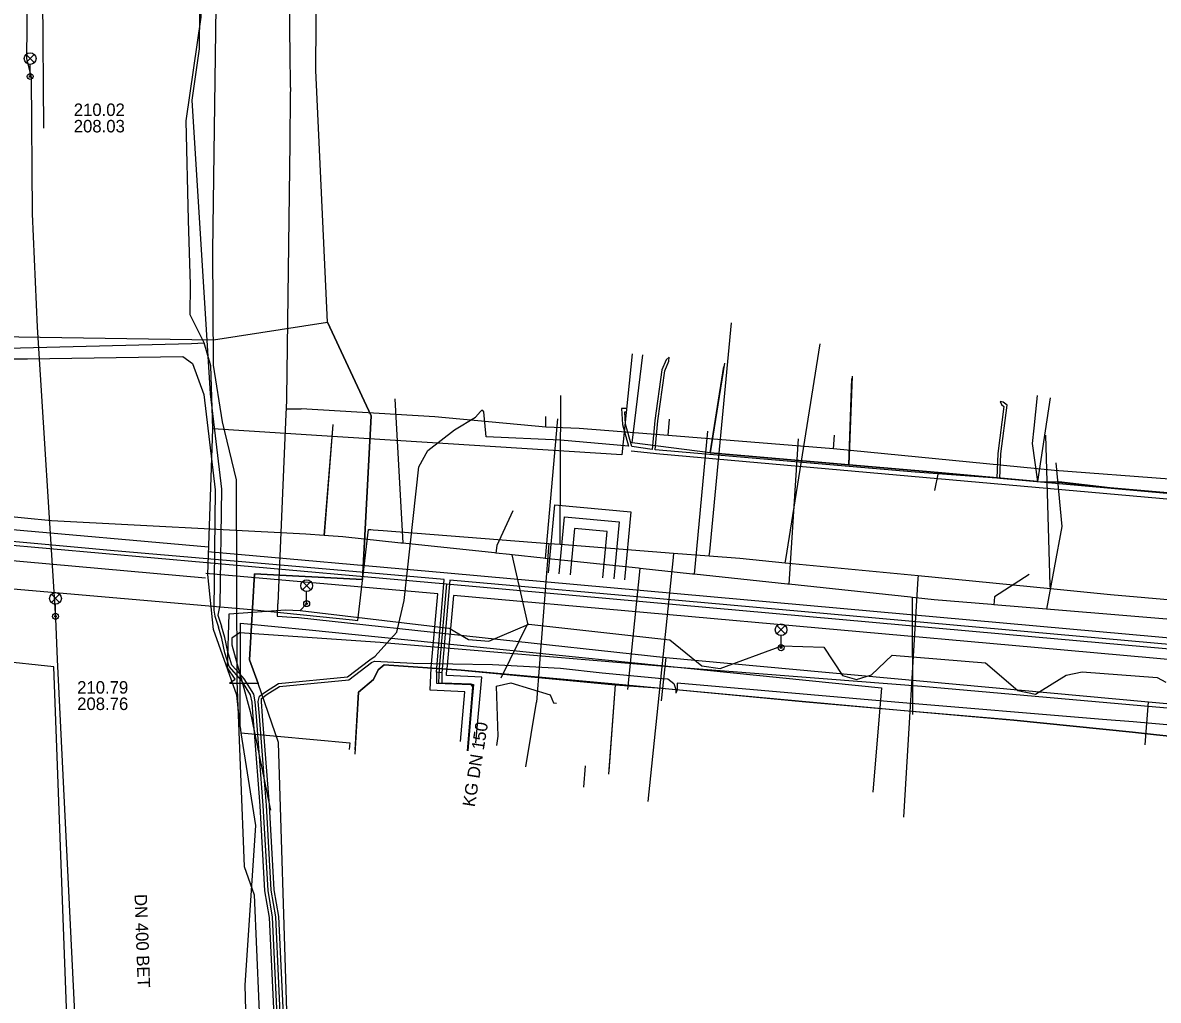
# Model space of a CAD drawing. Extents: x -596228 to -595156, y -1161235 to -1159373.
# Drawn here: x -595381.6 to -595308.9, y -1160980.9 to -1160918.3 of the extents above; entities that cross this region are included whole.
import ezdxf

# ---------------------------------------------------------------- set-up
doc = ezdxf.new("R2010")
doc.units = 0
for name, color, linetype in [('Vrstva 1', 7, 'Continuous'), ('Vrstva 12', 7, 'Continuous'), ('Vrstva 13', 7, 'Continuous'), ('Vrstva 14', 7, 'Continuous'), ('Vrstva 19', 7, 'Continuous'), ('Vrstva 25', 7, 'Continuous'), ('Vrstva 26', 7, 'Continuous'), ('Vrstva 30', 7, 'Continuous'), ('Vrstva 33', 7, 'Continuous'), ('Vrstva 4', 7, 'Continuous'), ('Vrstva 42', 7, 'Continuous'), ('Vrstva 5', 7, 'Continuous'), ('Vrstva 55', 7, 'Continuous'), ('Vrstva 58', 7, 'Continuous'), ('Vrstva 8', 7, 'Continuous'), ('Vrstva 9', 7, 'Continuous')]:
    doc.layers.add(name, color=color, linetype=linetype)

msp = doc.modelspace()

# ---------------------------------------------------------------- linework, layer by layer
at = {"layer": 'Vrstva 1'}
for p, q in [((-595380.27, -1160925.02), (-595380.587, -1160882.118)), ((-595361.765, -1160944.004), (-595362.33, -1160951.115)), ((-595361.77, -1160944), (-595362.315, -1160951.115)), ((-595379.64, -1160959.52), (-595405.794, -1160956.753)), ((-595377.69, -1161011.68), (-595379.64, -1160959.52)), ((-595345.694, -1160967.235), (-595345.58, -1160965.87))]:
    msp.add_line(p, q, dxfattribs=at)
for points in [[(-595350.229, -1160949.537), (-595351.264, -1160951.747), (-595351.317, -1160952.244)], [(-595350.229, -1160949.537), (-595351.264, -1160951.747), (-595351.317, -1160952.244)], [(-595317.17, -1160953.607), (-595319.381, -1160955.051), (-595319.423, -1160955.549)], [(-595317.17, -1160953.61), (-595319.381, -1160955.051), (-595319.423, -1160955.549)], [(-595351.31, -1160960.77), (-595350.37, -1160960.55), (-595347.85, -1160961.31), (-595347.63, -1160961.83), (-595347.442, -1160961.848)]]:
    msp.add_lwpolyline(points, dxfattribs=at)
at = {"layer": 'Vrstva 12'}
for p, q in [((-595336.68, -1160940.07), (-595337.6, -1160945.81)), ((-595328.51, -1160940.91), (-595328.71, -1160946.59)), ((-595316.643, -1160942.14), (-595316.86, -1160944.229)), ((-595316.86, -1160944.229), (-595316.963, -1160945.224)), ((-595316.963, -1160945.224), (-595316.62, -1160947.65)), ((-595337.6, -1160945.81), (-595328.71, -1160946.59)), ((-595328.71, -1160946.59), (-595323, -1160947.07)), ((-595323, -1160947.07), (-595323.22, -1160948.24)), ((-595323, -1160947.07), (-595316.62, -1160947.65)), ((-595343.67, -1160960.68), (-595344.09, -1160966.19))]:
    msp.add_line(p, q, dxfattribs=at)
for points in [[(-595371, -1160930.92), (-595371.16, -1160924.56), (-595370.19, -1160917.92), (-595369.95, -1160902.1), (-595370.25, -1160895.24), (-595369.91, -1160889.72), (-595369.62, -1160887.23)], [(-595369.44, -1160944.29), (-595369.58, -1160940.25), (-595370.01, -1160938.78), (-595370.9, -1160936.97), (-595370.88, -1160935.06), (-595371, -1160930.92)], [(-595342.59, -1160939.47), (-595343.25, -1160945.95), (-595362.46, -1160944.73), (-595369.44, -1160944.29)], [(-595337.6, -1160945.81), (-595342.6, -1160945.18), (-595341.9, -1160939.54)], [(-595367.69, -1160963.36), (-595367.91, -1160961.33), (-595369.41, -1160957.13), (-595369.77, -1160953.61), (-595369.44, -1160944.29)], [(-595316.62, -1160947.65), (-595315.26, -1160947.69), (-595311.97, -1160948.06), (-595303.88, -1160948.77)], [(-595367.69, -1160963.36), (-595367.67, -1160956.73), (-595363.28, -1160957.16), (-595326.63, -1160960.87), (-595327.17, -1160967.55)], [(-595360.33, -1160964.84), (-595360.12, -1160961.14), (-595359.16, -1160960.34), (-595358.85, -1160959.72), (-595358.47, -1160959.4), (-595353.55, -1160959.74), (-595344.12, -1160960.64), (-595343.67, -1160960.68)], [(-595343.67, -1160960.68), (-595340.7, -1160960.9), (-595331.47, -1160961.77), (-595325.4, -1160962.31), (-595318.15, -1160962.95), (-595310.55, -1160963.72), (-595309, -1160963.87), (-595307.34, -1160964.05)], [(-595367.69, -1160963.36), (-595367.65, -1160963.76), (-595366.71, -1160969.68), (-595367.4, -1160979.92), (-595366.8, -1161002.33), (-595366.29, -1161020.66), (-595365.09, -1161023.16)]]:
    msp.add_lwpolyline(points, dxfattribs=at)
at = {"layer": 'Vrstva 13'}
for points in [[(-595395.33, -1160939.24), (-595394.39, -1160939.34), (-595391.91, -1160939.34), (-595370.82, -1160938.81), (-595370.01, -1160938.78)], [(-595367.65, -1160963.76), (-595360.68, -1160964.39), (-595360.72, -1160964.81)]]:
    msp.add_lwpolyline(points, dxfattribs=at)
at = {"layer": 'Vrstva 14'}
for p, q in [((-595401.404, -1160952.842), (-595366.99, -1160955.862)), ((-595366.99, -1160955.862), (-595360.51, -1160956.52)), ((-595349.41, -1160965.94), (-595348.722, -1160961.788))]:
    msp.add_line(p, q, dxfattribs=at)
for points in [[(-595337.656, -1160952.418), (-595337.62, -1160952.14), (-595336.229, -1160937.487)], [(-595332.784, -1160952.855), (-595332.75, -1160952.654), (-595330.552, -1160938.832)], [(-595347.2, -1160951.678), (-595347.198, -1160951.528), (-595347.16, -1160942.15)], [(-595315.808, -1160954.514), (-595315.817, -1160954.307), (-595316.1, -1160944.69)], [(-595360.51, -1160956.52), (-595360.157, -1160956.561), (-595359.48, -1160950.72), (-595359.33, -1160950.733)], [(-595359.33, -1160950.733), (-595359.177, -1160950.746), (-595358.53, -1160950.8), (-595347.93, -1160951.621), (-595347.2, -1160951.678), (-595339.947, -1160952.24), (-595337.656, -1160952.418), (-595335.7, -1160952.57), (-595332.784, -1160952.855), (-595324.277, -1160953.686), (-595315.808, -1160954.514), (-595311.96, -1160954.89), (-595304.861, -1160955.516)], [(-595347.93, -1160951.621), (-595347.95, -1160951.88), (-595348.722, -1160961.788)], [(-595339.947, -1160952.24), (-595339.974, -1160952.52), (-595341.58, -1160968.155)], [(-595324.277, -1160953.686), (-595324.286, -1160953.873), (-595325.222, -1160969.157)]]:
    msp.add_lwpolyline(points, dxfattribs=at)
at = {"layer": 'Vrstva 19'}
for p, q in [((-595364.47, -1160922.43), (-595364.49, -1160922.96)), ((-595348.11, -1160944.18), (-595348.13, -1160943.5)), ((-595340.28, -1160944.7), (-595340.2, -1160943.67)), ((-595329.7, -1160945.56), (-595329.63, -1160944.69)), ((-595340.44, -1160958.93), (-595340.73, -1160961.71)), ((-595309.73, -1160964.53), (-595309.52, -1160961.76))]:
    msp.add_line(p, q, dxfattribs=at)
for points in [[(-595364.47, -1160922.43), (-595364.47, -1160922.01), (-595364.49, -1160920.51), (-595364.54, -1160916.5), (-595367.18, -1160916.4)], [(-595364.49, -1160922.96), (-595364.51, -1160925.89), (-595364.51, -1160925.97), (-595364.73, -1160942.3), (-595364.731, -1160942.38), (-595364.76, -1160943), (-595364.772, -1160943.281), (-595364.774, -1160943.339), (-595365.296, -1160955.473), (-595365.298, -1160955.529), (-595365.33, -1160956.27), (-595364.386, -1160956.339), (-595363.97, -1160956.37)], [(-595364.76, -1160943), (-595364.7, -1160943), (-595364.19, -1160943), (-595363.8, -1160943)], [(-595200.02, -1160957.4), (-595204.53, -1160957.01), (-595210.4, -1160956.507), (-595212.31, -1160956.343), (-595219.58, -1160955.72), (-595225.2, -1160955.1), (-595236.06, -1160954.1), (-595246.4, -1160953.24), (-595264.63, -1160951.54), (-595268.38, -1160951.19), (-595278.55, -1160950.31), (-595285.68, -1160949.7), (-595297.2, -1160948.43), (-595300.81, -1160948.06), (-595315.54, -1160946.95), (-595329.7, -1160945.56), (-595340.28, -1160944.7), (-595345.98, -1160944.26), (-595348.11, -1160944.18), (-595355.24, -1160943.52), (-595363.8, -1160943)], [(-595363.97, -1160956.37), (-595340.44, -1160958.93), (-595309.52, -1160961.76), (-595287.05, -1160963.81), (-595273.8, -1160964.93), (-595267.16, -1160965.55), (-595248.5, -1160967.29), (-595238, -1160968.22), (-595226.95, -1160969.21), (-595226.945, -1160969.21), (-595226.94, -1160969.21), (-595214.64, -1160970.27), (-595201.6, -1160971.47), (-595183.51, -1160973.15), (-595162.55, -1160974.77), (-595158.23, -1160975.101)]]:
    msp.add_lwpolyline(points, dxfattribs=at)
at = {"layer": 'Vrstva 25'}
for p, q in [((-595394.096, -1160950.669), (-595369.825, -1160952.84)), ((-595369.825, -1160952.84), (-595354.475, -1160954.205)), ((-595354.475, -1160954.205), (-595354.962, -1160959.61))]:
    msp.add_line(p, q, dxfattribs=at)
for points in [[(-595347.257, -1160953.567), (-595346.916, -1160949.911), (-595343.431, -1160950.23), (-595343.772, -1160953.89)], [(-595354.475, -1160954.205), (-595316.75, -1160957.598), (-595259.515, -1160962.731), (-595220.972, -1160966.142), (-595210.587, -1160967.058)], [(-595354.962, -1160959.61), (-595355.005, -1160960.543), (-595352.761, -1160960.663), (-595353.094, -1160964.344)]]:
    msp.add_lwpolyline(points, dxfattribs=at)
at = {"layer": 'Vrstva 26'}
for p, q in [((-595394.007, -1160949.673), (-595369.736, -1160951.844)), ((-595369.914, -1160953.836), (-595394.081, -1160951.674)), ((-595369.763, -1160952.143), (-595354.413, -1160953.508)), ((-595355.036, -1160954.858), (-595369.887, -1160953.537)), ((-595355.46, -1160959.565), (-595355.036, -1160954.858)), ((-595354.04, -1160954.947), (-595354.464, -1160959.655))]:
    msp.add_line(p, q, dxfattribs=at)
for points in [[(-595347.954, -1160953.502), (-595347.548, -1160949.15), (-595342.669, -1160949.597), (-595343.075, -1160953.954)], [(-595344.469, -1160953.825), (-595344.193, -1160950.863), (-595346.284, -1160950.672), (-595346.56, -1160953.632)], [(-595354.412, -1160953.508), (-595316.688, -1160956.901), (-595259.453, -1160962.034), (-595220.91, -1160965.445), (-595210.525, -1160966.361)], [(-595210.648, -1160967.756), (-595221.033, -1160966.839), (-595259.577, -1160963.428), (-595316.813, -1160958.296), (-595354.04, -1160954.947)], [(-595353.592, -1160964.299), (-595353.306, -1160961.135), (-595355.527, -1160961.015), (-595355.461, -1160959.587)], [(-595352.596, -1160964.389), (-595352.216, -1160960.192), (-595354.482, -1160960.07), (-595354.462, -1160959.633)]]:
    msp.add_lwpolyline(points, dxfattribs=at)
at = {"layer": 'Vrstva 30'}
msp.add_lwpolyline([(-595158.23, -1160971.393), (-595167.346, -1160970.62), (-595179.41, -1160969.563), (-595195.568, -1160968.175), (-595221.306, -1160965.838), (-595271.405, -1160961.411), (-595302.964, -1160958.559), (-595339.394, -1160955.295), (-595354.278, -1160953.973), (-595354.781, -1160959.902), (-595355.123, -1160959.872), (-595354.625, -1160953.942), (-595365.606, -1160952.967), (-595375.771, -1160952.1), (-595394.433, -1160950.38)], dxfattribs=at)
at = {"layer": 'Vrstva 33'}
for p, q in [((-595381.413, -1160920.3), (-595380.883, -1160920.83)), ((-595381.413, -1160920.83), (-595380.883, -1160920.3)), ((-595381.148, -1160921.715), (-595381.148, -1160920.94)), ((-595363.705, -1160954.065), (-595363.175, -1160954.595)), ((-595363.705, -1160954.595), (-595363.175, -1160954.065)), ((-595379.791, -1160954.88), (-595379.261, -1160955.41)), ((-595379.791, -1160955.41), (-595379.261, -1160954.88)), ((-595363.44, -1160955.48), (-595363.44, -1160954.705)), ((-595379.526, -1160956.295), (-595379.526, -1160955.52)), ((-595333.315, -1160956.885), (-595332.785, -1160957.415)), ((-595333.315, -1160957.415), (-595332.785, -1160956.885)), ((-595333.05, -1160958.3), (-595333.05, -1160957.525))]:
    msp.add_line(p, q, dxfattribs=at)
for centre, radius in [((-595381.148, -1160920.565), 0.375), ((-595381.148, -1160921.715), 0.19), ((-595381.148, -1160921.715), 0.05), ((-595363.44, -1160954.33), 0.375), ((-595379.526, -1160955.145), 0.375), ((-595363.44, -1160955.48), 0.19), ((-595363.44, -1160955.48), 0.05), ((-595379.526, -1160956.295), 0.19), ((-595379.526, -1160956.295), 0.05), ((-595333.05, -1160957.15), 0.375), ((-595333.05, -1160958.3), 0.19), ((-595333.05, -1160958.3), 0.05)]:
    msp.add_circle(centre, radius, dxfattribs=at)
at = {"layer": 'Vrstva 42'}
for points in [[(-595368.95, -1160798.91), (-595368.74, -1160814.52), (-595368.85, -1160831.39), (-595368.79, -1160845.22), (-595369.91, -1160847.75), (-595368.62, -1160849.92), (-595368.6, -1160857.77), (-595369.97, -1160860.72), (-595369.8, -1160862.36), (-595368.62, -1160864.61), (-595368.7, -1160876.19), (-595368.84, -1160894.98), (-595369.21, -1160914.12), (-595369.46, -1160932.88), (-595369.43, -1160940.2), (-595368.85, -1160943.84), (-595367.96, -1160947.54), (-595367.92, -1160960.44), (-595367.44, -1160972.31), (-595366.8, -1160974.13), (-595366.35, -1160984.63)], [(-595360.976, -1160888.219), (-595361.748, -1160888.179), (-595361.844, -1160888.189), (-595368.497, -1160888.71), (-595370.195, -1160905.271), (-595370.327, -1160919.944), (-595370.786, -1160923.222), (-595369.629, -1160942.031), (-595368.904, -1160948.154), (-595369, -1160955.571), (-595369.135, -1160956.208), (-595368.895, -1160956.92)], [(-595412.458, -1160937.816), (-595412.52, -1160938.6), (-595410.509, -1160939.258), (-595409.781, -1160938.884), (-595408.35, -1160938.352), (-595391.478, -1160939.84), (-595385.196, -1160939.809), (-595381.329, -1160939.79), (-595371.367, -1160939.639), (-595370.742, -1160940.089), (-595370.027, -1160942.079), (-595369.304, -1160948.18), (-595369.392, -1160955.891), (-595369.325, -1160956.272), (-595369.085, -1160956.98)], [(-595304.54, -1160948.761), (-595319.04, -1160947.459), (-595318.97, -1160945.889), (-595318.574, -1160942.756), (-595318.823, -1160942.565), (-595319.02, -1160942.54), (-595318.945, -1160942.723), (-595318.786, -1160942.844), (-595319.17, -1160945.871), (-595319.24, -1160947.443), (-595324.46, -1160947.05), (-595341.11, -1160945.619), (-595340.951, -1160943.761), (-595340.503, -1160940.558), (-595340.234, -1160939.947), (-595340.23, -1160939.69), (-595340.418, -1160939.867), (-595340.697, -1160940.502), (-595341.149, -1160943.739), (-595341.309, -1160945.596), (-595342.622, -1160945.415), (-595343.011, -1160943.973), (-595343.063, -1160943.19), (-595342.938, -1160943.189)], [(-595366.458, -1160961.406), (-595366.077, -1160961.118), (-595365.244, -1160960.583), (-595360.818, -1160960.163), (-595359.401, -1160959.081), (-595359.055, -1160958.845), (-595358.295, -1160958.003), (-595357.66, -1160957.3), (-595357.19, -1160955.28), (-595356.26, -1160946.71), (-595355.68, -1160945.67), (-595353.98, -1160944.35), (-595352.63, -1160943.54), (-595352.301, -1160943.162), (-595352.21, -1160943.08)], [(-595342.907, -1160942.99), (-595343.277, -1160942.99), (-595343.209, -1160944.007), (-595342.836, -1160945.391), (-595347.19, -1160945.01), (-595351.949, -1160944.785), (-595352.098, -1160943.197), (-595352.21, -1160943.08)], [(-595201.581, -1160958.399), (-595220.256, -1160956.831), (-595236.768, -1160955.237), (-595265.542, -1160952.714), (-595267.019, -1160952.493), (-595280.318, -1160951.294), (-595281.646, -1160951.162), (-595296.625, -1160949.865), (-595305.214, -1160949.064), (-595340.816, -1160945.901), (-595342.657, -1160945.705)], [(-595355.126, -1160959.857), (-595354.625, -1160953.942), (-595365.606, -1160952.967), (-595375.771, -1160952.1), (-595394.433, -1160950.38)], [(-595158.23, -1160971.393), (-595167.346, -1160970.62), (-595179.41, -1160969.563), (-595195.568, -1160968.175), (-595221.306, -1160965.838), (-595271.405, -1160961.411), (-595302.964, -1160958.559), (-595339.394, -1160955.295), (-595354.278, -1160953.973), (-595354.781, -1160959.902)], [(-595365.42, -1160984.107), (-595365.819, -1160975.572), (-595366.109, -1160973.874), (-595366.419, -1160968.42), (-595366.781, -1160963.739), (-595366.859, -1160962.724), (-595366.939, -1160961.785), (-595367.033, -1160961.325), (-595367.596, -1160960.432), (-595367.61, -1160960.41), (-595368.399, -1160959.51), (-595368.687, -1160958.626), (-595368.877, -1160957.704), (-595369.085, -1160956.98)], [(-595365.22, -1160984.096), (-595365.62, -1160975.551), (-595365.91, -1160973.851), (-595366.22, -1160968.407), (-595366.46, -1160965.297), (-595366.66, -1160962.708), (-595366.74, -1160961.768), (-595366.827, -1160961.276), (-595367.45, -1160960.29), (-595367.72, -1160959.981), (-595368.221, -1160959.41), (-595368.493, -1160958.574), (-595368.683, -1160957.656), (-595368.895, -1160956.92)], [(-595227.521, -1160970.201), (-595227.416, -1160969.613), (-595227.663, -1160969.46), (-595255.573, -1160966.976), (-595281.98, -1160964.626), (-595306.374, -1160962.341), (-595324.029, -1160960.787), (-595340.518, -1160959.508), (-595358.295, -1160958.003), (-595358.738, -1160957.965), (-595367.748, -1160957.354), (-595368.221, -1160957.694), (-595368.231, -1160958.122), (-595367.72, -1160959.981), (-595367.596, -1160960.432), (-595367.058, -1160962.392), (-595366.781, -1160963.739), (-595366.46, -1160965.297), (-595366.139, -1160966.855), (-595365.819, -1160968.409), (-595365.757, -1160968.71)], [(-595366.322, -1160961.554), (-595365.963, -1160961.282), (-595365.176, -1160960.777), (-595360.742, -1160960.357), (-595359.279, -1160959.239), (-595359.1, -1160959.172), (-595356.61, -1160959.3), (-595351.53, -1160959.38), (-595347.18, -1160959.61), (-595344.51, -1160959.92), (-595340.68, -1160960.28), (-595340.3, -1160960.29), (-595339.92, -1160960.59), (-595339.794, -1160960.982), (-595339.8, -1160961.21)], [(-595355.126, -1160959.857), (-595355.126, -1160960.576), (-595352.914, -1160960.655), (-595352.817, -1160960.803), (-595353.162, -1160964.901)], [(-595354.781, -1160959.902), (-595354.781, -1160960.436), (-595354.781, -1160960.546), (-595352.88, -1160960.619), (-595352.769, -1160960.801), (-595353.114, -1160964.904)], [(-595306.24, -1160963.65), (-595306.89, -1160963.55), (-595307.394, -1160963.331), (-595310.5, -1160963.05), (-595312.47, -1160962.89), (-595325.77, -1160961.78), (-595339.71, -1160960.579), (-595339.703, -1160961.007), (-595339.8, -1160961.21)], [(-595365.02, -1160984.084), (-595365.42, -1160975.529), (-595365.71, -1160973.829), (-595366.02, -1160968.393), (-595366.139, -1160966.855), (-595366.46, -1160962.692), (-595366.54, -1160961.751), (-595366.458, -1160961.406)], [(-595364.82, -1160984.073), (-595365.221, -1160975.508), (-595365.511, -1160973.806), (-595365.819, -1160968.409), (-595365.821, -1160968.38), (-595366.261, -1160962.676), (-595366.341, -1160961.735), (-595366.322, -1160961.554)]]:
    msp.add_lwpolyline(points, dxfattribs=at)
at = {"layer": 'Vrstva 5'}
for p, q in [((-595357.786, -1160942.351), (-595357.288, -1160951.609)), ((-595347.369, -1160943.635), (-595348.169, -1160952.579)), ((-595337.767, -1160944.426), (-595338.613, -1160953.596)), ((-595331.956, -1160944.917), (-595332.548, -1160954.241)), ((-595342.865, -1160960.986), (-595342.074, -1160953.227)), ((-595324.616, -1160962.574), (-595324.642, -1160955.082))]:
    msp.add_line(p, q, dxfattribs=at)
for points in [[(-595315.451, -1160946.462), (-595315.071, -1160950.534), (-595316.064, -1160955.829)], [(-595350.983, -1160960.227), (-595349.269, -1160956.746), (-595350.277, -1160952.355)], [(-595351.31, -1160960.77), (-595351.19, -1160963.96), (-595351.29, -1160964.56)]]:
    msp.add_lwpolyline(points, dxfattribs=at)
at = {"layer": 'Vrstva 55'}
for points in [[(-595379.39, -1160802.14), (-595379.54, -1160809.29), (-595379.69, -1160816.42), (-595379.81, -1160823.57), (-595379.95, -1160830.73), (-595380.1, -1160837.86), (-595380.22, -1160844.96), (-595380.37, -1160852.09), (-595380.52, -1160859.32), (-595380.64, -1160866.45), (-595380.79, -1160873.58), (-595381.01, -1160887.74), (-595381.11, -1160894.92), (-595381.18, -1160902.05), (-595381.28, -1160909.18), (-595381.35, -1160916.31), (-595381.38, -1160920.58), (-595381.079, -1160921.749), (-595381.01, -1160930.52), (-595380.71, -1160937.78), (-595379.526, -1160956.433), (-595379.423, -1160959.056), (-595377.97, -1160988.68)], [(-595368.38, -1160960.57), (-595366.535, -1160960.59), (-595367.1, -1160959.08), (-595366.79, -1160953.56), (-595359.87, -1160953.93), (-595359.3, -1160943.45), (-595362.11, -1160937.46), (-595362.843, -1160921.325), (-595362.687, -1160896.538), (-595361.44, -1160886.092), (-595361.51, -1160885.81)], [(-595401.12, -1161017.19), (-595396.08, -1161009.89), (-595394.21, -1160998.66), (-595395.259, -1160988.029), (-595395.52, -1160974.14), (-595394.961, -1160962.237), (-595392.43, -1160943.26), (-595393, -1160938.21), (-595369.41, -1160938.58), (-595362.11, -1160937.46), (-595359.3, -1160943.45), (-595359.87, -1160953.93), (-595366.79, -1160953.56), (-595367.1, -1160959.08), (-595366.535, -1160960.59), (-595368.38, -1160960.57)], [(-595368.38, -1160960.57), (-595368.02, -1160960.32), (-595368.51, -1160959.58), (-595368.4, -1160956.14), (-595364.79, -1160955.87), (-595363.85, -1160955.91), (-595363.44, -1160955.48), (-595363.85, -1160955.91), (-595354.32, -1160957.05), (-595353.08, -1160957.77), (-595351.77, -1160957.89), (-595349.2, -1160956.8), (-595340.18, -1160957.8), (-595338.13, -1160959.47), (-595336.96, -1160959.63), (-595333.01, -1160958.17), (-595333.05, -1160958.3), (-595333.01, -1160958.17), (-595330.31, -1160958.26), (-595329.13, -1160960.07), (-595328.22, -1160960.33), (-595327.26, -1160960.03), (-595325.93, -1160958.78), (-595319.97, -1160959.27), (-595317.88, -1160961.05), (-595316.76, -1160961.28), (-595314.8, -1160960.05), (-595313.77, -1160959.85), (-595308.96, -1160960.21), (-595308.41, -1160960.5)], [(-595364.17, -1160998.78), (-595365.24, -1160964.37), (-595366.535, -1160960.59), (-595368.38, -1160960.57)]]:
    msp.add_lwpolyline(points, dxfattribs=at)
at = {"layer": 'Vrstva 58'}
for p, q in [((-595328.708, -1160946.586), (-595328.514, -1160941.055)), ((-595316.624, -1160947.65), (-595315.26, -1160947.685)), ((-595311.966, -1160948.059), (-595315.26, -1160947.685)), ((-595340.704, -1160960.904), (-595344.12, -1160960.598)), ((-595343.674, -1160960.675), (-595344.109, -1160966.398)), ((-595309.003, -1160963.872), (-595310.553, -1160963.715)), ((-595307.335, -1160964.048), (-595309.003, -1160963.872))]:
    msp.add_line(p, q, dxfattribs=at)
for points in [[(-595315.812, -1160942.291), (-595316.624, -1160947.65), (-595323.002, -1160947.073), (-595328.708, -1160946.586), (-595337.598, -1160945.81), (-595336.715, -1160940.293)], [(-595256.887, -1160952.932), (-595257.865, -1160952.886), (-595267.114, -1160952.057), (-595268.905, -1160951.878), (-595275.761, -1160951.257), (-595280.944, -1160950.767), (-595283.627, -1160950.582), (-595298.27, -1160949.235), (-595303.882, -1160948.768), (-595311.966, -1160948.059)], [(-595344.12, -1160960.598), (-595353.551, -1160959.74), (-595358.47, -1160959.397), (-595358.854, -1160959.715), (-595359.164, -1160960.336), (-595360.119, -1160961.143), (-595360.353, -1160965.123)], [(-595310.553, -1160963.715), (-595318.15, -1160962.95), (-595325.4, -1160962.313), (-595331.47, -1160961.768), (-595340.704, -1160960.904)]]:
    msp.add_lwpolyline(points, dxfattribs=at)
at = {"layer": 'Vrstva 9'}
for p, q in [((-595357.786, -1160942.351), (-595357.288, -1160951.609)), ((-595347.369, -1160943.635), (-595348.169, -1160952.579)), ((-595337.767, -1160944.426), (-595338.613, -1160953.596)), ((-595331.956, -1160944.917), (-595332.548, -1160954.241)), ((-595379.773, -1160950.169), (-595405.067, -1160947.744)), ((-595363.5, -1160951.03), (-595379.773, -1160950.169)), ((-595342.865, -1160960.986), (-595342.074, -1160953.227)), ((-595324.616, -1160962.574), (-595324.642, -1160955.082))]:
    msp.add_line(p, q, dxfattribs=at)
for points in [[(-595315.451, -1160946.462), (-595315.071, -1160950.534), (-595316.064, -1160955.829)], [(-595361.13, -1160951.2), (-595362.03, -1160951.135), (-595362.315, -1160951.115), (-595363.5, -1160951.03)], [(-595323.25, -1160955.23), (-595324.642, -1160955.082), (-595324.765, -1160955.069), (-595332.548, -1160954.241), (-595332.641, -1160954.231), (-595338.613, -1160953.596), (-595338.736, -1160953.582), (-595342.074, -1160953.227), (-595342.177, -1160953.216), (-595348.169, -1160952.579), (-595348.283, -1160952.567), (-595350.277, -1160952.355), (-595350.44, -1160952.337), (-595351.317, -1160952.244), (-595351.415, -1160952.234), (-595357.288, -1160951.609), (-595357.401, -1160951.597), (-595361.13, -1160951.2)], [(-595350.983, -1160960.227), (-595349.269, -1160956.746), (-595350.277, -1160952.355)], [(-595282.56, -1160958.62), (-595287.267, -1160958.228), (-595287.314, -1160958.224), (-595288.202, -1160958.15), (-595288.36, -1160958.137), (-595299.298, -1160957.226), (-595299.302, -1160957.225), (-595300.273, -1160957.144), (-595300.338, -1160957.139), (-595304.98, -1160956.752), (-595304.992, -1160956.751), (-595316.055, -1160955.829), (-595316.064, -1160955.829), (-595319.423, -1160955.549), (-595319.578, -1160955.536), (-595323.25, -1160955.23)]]:
    msp.add_lwpolyline(points, dxfattribs=at)

# ---------------------------------------------------------------- texts
at = {"layer": 'Vrstva 4'}
for s, p in [('210.02', (-595378.356, -1160924.246)), ('208.03', (-595378.356, -1160925.296)), ('210.79', (-595378.138, -1160961.242)), ('208.76', (-595378.138, -1160962.292))]:
    msp.add_text(s, height=0.8, dxfattribs=at).set_placement(p)
msp.add_text('DN 400 BET', height=0.8, rotation=272, dxfattribs=at).set_placement((-595374.468, -1160974.09))
at = {"layer": 'Vrstva 8'}
msp.add_text('KG DN 150', height=0.8, rotation=81, dxfattribs=at).set_placement((-595352.672, -1160968.533))

doc.saveas('drawing.dxf')
